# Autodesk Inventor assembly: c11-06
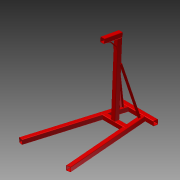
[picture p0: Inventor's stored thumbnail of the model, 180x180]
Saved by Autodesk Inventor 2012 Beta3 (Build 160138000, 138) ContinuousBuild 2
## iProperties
Created: 2011-01
Part Number: c11-06
Document SubType Name: Assembly
Designer: Beta-8540w
_SolveAssemblyDoc: Frame Generator Solve Assembly
_Version: 15.0.0
Author: Beta-8540w
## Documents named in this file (3)
- C:\Inventor 2012 Essentials\Assemblies\Chapter 11\c11-06.iam
- C:\Inventor 2012 Essentials\Parts\Chapter 11\c11-01.ipt
- C:\Inventor 2012 Essentials\Assemblies\Chapter 11\Frame\Frame c11-06.iam
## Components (2 placed, 2 different names)
1. c11-01:1
2. Frame c11-06:1 [sub-assembly]
